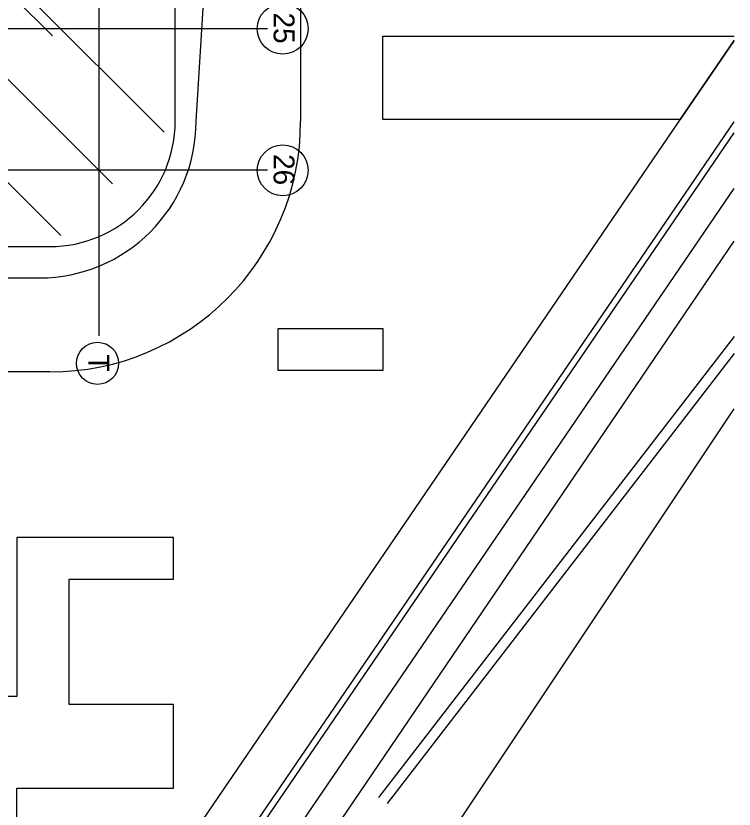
# Model space of a CAD drawing. Extents: x -264165 to -263575, y -1242333 to -1242036.
# Drawn here: x -263799.51 to -263765.16, y -1242271.38 to -1242233.41 of the extents above; entities that cross this region are included whole.
import ezdxf

# ---------------------------------------------------------------- set-up
doc = ezdxf.new("R2010")
doc.units = 0
doc.layers.add('KFA_HESCON_OSI_STAVBY', color=7, linetype='Continuous')
doc.layers.add('KFA_SITUACIA_DRS_VYTYCOVAK_SEDA', color=7, linetype='Continuous')

msp = doc.modelspace()

# ---------------------------------------------------------------- linework, layer by layer
at = {"layer": 'KFA_HESCON_OSI_STAVBY'}
for p, q in [((-263795.543, -1242080.447), (-263795.543, -1242248.737)), ((-263819.468, -1242216.882), (-263794.893, -1242241.457)), ((-263792.418, -1242238.982), (-263810.471, -1242220.93)), ((-263797.368, -1242243.932), (-263815.42, -1242225.879)), ((-263787.486, -1242234.032), (-263921.823, -1242234.032)), ((-263787.486, -1242234.032), (-263787.486, -1242234.032)), ((-263792.418, -1242238.982), (-263792.418, -1242238.982)), ((-263787.486, -1242240.807), (-263921.823, -1242240.807)), ((-263787.486, -1242240.807), (-263787.486, -1242240.807)), ((-263797.368, -1242243.932), (-263797.368, -1242243.932))]:
    msp.add_line(p, q, dxfattribs=at)
for centre, radius in [((-263786.751, -1242234.032), 1.216), ((-263786.751, -1242240.807), 1.216), ((-263795.608, -1242250.045), 1.008)]:
    msp.add_circle(centre, radius, dxfattribs=at)
at = {"layer": 'KFA_SITUACIA_DRS_VYTYCOVAK_SEDA'}
for p, q in [((-263791.893, -1242238.458), (-263791.893, -1242228.625)), ((-263790.893, -1242238.458), (-263790.279, -1242228.625)), ((-263785.893, -1242228.625), (-263785.893, -1242238.458)), ((-263799.862, -1242232.281), (-263797.765, -1242234.377)), ((-263799.862, -1242232.281), (-263797.765, -1242234.377)), ((-263798.899, -1242284.125), (-263765.158, -1242234.596)), ((-263798.899, -1242284.125), (-263765.158, -1242234.596)), ((-263781.968, -1242238.382), (-263781.968, -1242234.382)), ((-263781.968, -1242234.382), (-263765.158, -1242234.382)), ((-263781.968, -1242234.382), (-263771.968, -1242234.382)), ((-263781.968, -1242238.382), (-263781.968, -1242234.382)), ((-263771.968, -1242234.382), (-263765.158, -1242234.382)), ((-263767.738, -1242238.382), (-263765.158, -1242234.596)), ((-263765.158, -1242234.596), (-263767.738, -1242238.382)), ((-263767.738, -1242238.382), (-263781.968, -1242238.382)), ((-263771.968, -1242238.382), (-263781.968, -1242238.382)), ((-263767.738, -1242238.382), (-263771.968, -1242238.382)), ((-263798.268, -1242287.038), (-263765.158, -1242238.482)), ((-263798.027, -1242287.218), (-263765.158, -1242239.015)), ((-263796.825, -1242288.118), (-263765.158, -1242241.677)), ((-263796.825, -1242288.118), (-263765.158, -1242241.677)), ((-263807.725, -1242244.458), (-263797.893, -1242244.458)), ((-263794.898, -1242288.031), (-263765.158, -1242244.196)), ((-263808.225, -1242245.958), (-263798.393, -1242245.958)), ((-263786.968, -1242248.382), (-263781.968, -1242248.382)), ((-263786.968, -1242250.382), (-263786.968, -1242248.382)), ((-263786.968, -1242248.382), (-263781.968, -1242248.382)), ((-263786.968, -1242250.382), (-263786.968, -1242248.382)), ((-263781.968, -1242248.382), (-263781.968, -1242250.382)), ((-263781.968, -1242248.382), (-263781.968, -1242250.382)), ((-263765.158, -1242248.762), (-263782.166, -1242270.821)), ((-263765.158, -1242249.58), (-263781.759, -1242271.113)), ((-263797.893, -1242250.458), (-263807.725, -1242250.458)), ((-263781.968, -1242250.382), (-263786.968, -1242250.382)), ((-263781.968, -1242250.382), (-263786.968, -1242250.382)), ((-263779.852, -1242274.272), (-263765.158, -1242252.228)), ((-263791.968, -1242258.382), (-263799.468, -1242258.382)), ((-263799.468, -1242258.382), (-263799.468, -1242265.987)), ((-263791.968, -1242258.382), (-263799.468, -1242258.382)), ((-263799.468, -1242258.382), (-263799.468, -1242265.987)), ((-263791.968, -1242260.382), (-263791.968, -1242258.382)), ((-263791.968, -1242260.382), (-263791.968, -1242258.382)), ((-263796.968, -1242266.382), (-263796.968, -1242260.382)), ((-263796.968, -1242260.382), (-263791.968, -1242260.382)), ((-263796.968, -1242266.382), (-263796.968, -1242260.382)), ((-263796.968, -1242260.382), (-263791.968, -1242260.382)), ((-263799.468, -1242265.987), (-263802.068, -1242265.987)), ((-263799.468, -1242265.987), (-263802.068, -1242265.987)), ((-263791.968, -1242266.382), (-263796.968, -1242266.382)), ((-263791.968, -1242266.382), (-263796.968, -1242266.382)), ((-263791.968, -1242270.382), (-263791.968, -1242266.382)), ((-263791.968, -1242270.382), (-263791.968, -1242266.382)), ((-263799.468, -1242274.382), (-263799.468, -1242270.382)), ((-263799.468, -1242270.382), (-263791.968, -1242270.382)), ((-263799.468, -1242274.382), (-263799.468, -1242270.382)), ((-263799.468, -1242270.382), (-263791.968, -1242270.382))]:
    msp.add_line(p, q, dxfattribs=at)
for centre, radius in [((-263798.393, -1242238.458), 7.5), ((-263797.893, -1242238.458), 6), ((-263797.893, -1242238.458), 12)]:
    msp.add_arc(centre, radius, 270, 0, dxfattribs=at)

# ---------------------------------------------------------------- texts
at = {"layer": 'KFA_HESCON_OSI_STAVBY'}
for s, p in [('25', (-263787.186, -1242233.255)), ('26', (-263787.186, -1242240.03)), ('T', (-263796.043, -1242249.619))]:
    msp.add_text(s, height=1, rotation=270, dxfattribs=at).set_placement(p)

doc.saveas('drawing.dxf')
